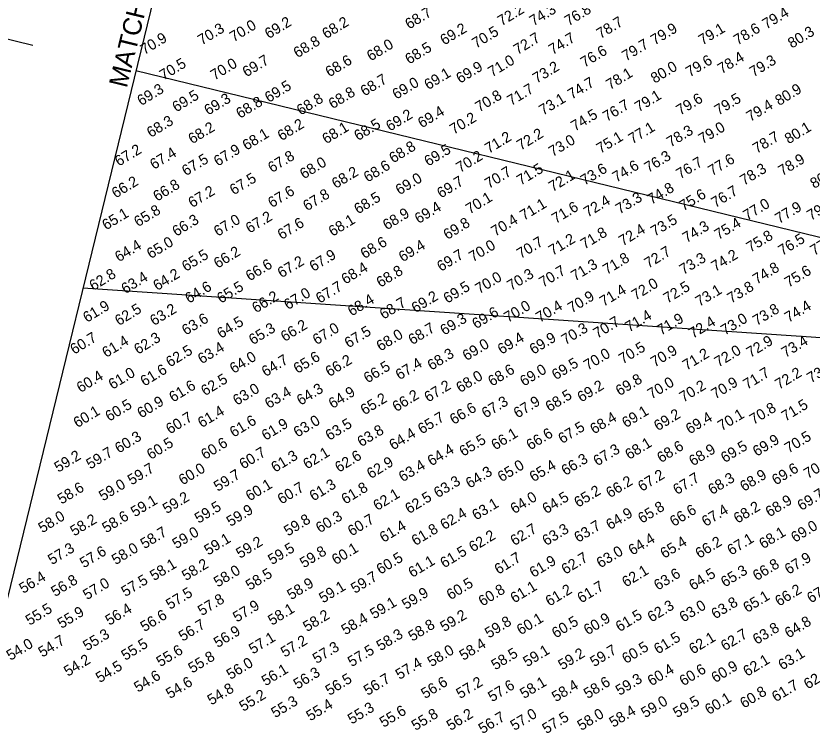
# Model space of a CAD drawing. Extents: x 403671 to 408751, y 1189919 to 1194265.
# Drawn here: x 404728 to 405477, y 1191442 to 1192117 of the extents above; entities that cross this region are included whole.
import ezdxf

# ---------------------------------------------------------------- set-up
doc = ezdxf.new("R2010")
doc.units = 0
for name, color, linetype in [('C-CHAN-POIT', 7, 'Continuous'), ('C-CHAN-WIDE', 7, 'Continuous'), ('V-ALGN-TEXT', 7, 'Continuous'), ('V-ANNO-MATC', 7, 'Continuous'), ('V-ANNO-MATC-IDEN', 7, 'Continuous'), ('V-TOPO-SOUN', 7, 'Continuous')]:
    doc.layers.add(name, color=color, linetype=linetype)

msp = doc.modelspace()

# ---------------------------------------------------------------- linework, layer by layer
at = {"layer": 'C-CHAN-POIT'}
msp.add_line((404840.85, 1192065.98), (406017.44, 1191779.04), dxfattribs=at)
at = {"layer": 'C-CHAN-WIDE'}
msp.add_line((404790.92, 1191861.25), (406017.44, 1191779.04), dxfattribs=at)
at = {"layer": 'V-ALGN-TEXT'}
msp.add_line((404646.55, 1192113.36), (404743.7, 1192089.67), dxfattribs=at)
at = {"layer": 'V-ANNO-MATC'}
msp.add_line((405089.63, 1193086.08), (404704.35, 1191506.27), dxfattribs=at)

# ---------------------------------------------------------------- texts
at = {"layer": 'V-ANNO-MATC-IDEN'}
msp.add_text('MATCHLINE SHEET NO. 024 STA. 6+00 EGMONT CUT-2', height=17.52, rotation=76.29456, dxfattribs=at).set_placement((404832.14, 1192048.75))
at = {"layer": 'V-TOPO-SOUN'}
for s, p in [('72.2 ', (405184.75, 1192107.31)), ('74.3 ', (405214.77, 1192107.31)), ('76.8 ', (405247.78, 1192107.31)), ('68.7 ', (405097.78, 1192104.32)), ('79.4 ', (405433.77, 1192104.32)), ('70.0 ', (404932.78, 1192092.32)), ('69.2 ', (404965.76, 1192095.3)), ('68.2 ', (405019.76, 1192095.3)), ('78.7 ', (405277.76, 1192095.3)), ('70.3 ', (404902.76, 1192089.3)), ('69.2 ', (405130.78, 1192089.3)), ('70.5 ', (405160.77, 1192086.31)), ('79.9 ', (405328.78, 1192089.3)), ('79.1 ', (405373.76, 1192089.3)), ('78.6 ', (405406.77, 1192089.3)), ('80.3 ', (405457.78, 1192086.31)), ('70.9 ', (404848.76, 1192080.31)), ('68.8 ', (404992.76, 1192077.32)), ('72.7 ', (405199.78, 1192080.31)), ('74.7 ', (405232.78, 1192080.31)), ('68.0 ', (405061.75, 1192074.3)), ('68.5 ', (405097.78, 1192071.32)), ('76.6 ', (405262.77, 1192068.3)), ('79.7 ', (405301.78, 1192074.3)), ('78.4 ', (405391.77, 1192062.3)), ('70.5 ', (404866.77, 1192056.29)), ('70.0 ', (404914.77, 1192056.29)), ('69.7 ', (404944.76, 1192059.31)), ('68.6 ', (405022.78, 1192059.31)), ('69.9 ', (405145.77, 1192053.31)), ('71.0 ', (405175.76, 1192059.31)), ('73.2 ', (405217.76, 1192053.31)), ('80.0 ', (405328.78, 1192053.31)), ('79.6 ', (405361.75, 1192059.31)), ('79.3 ', (405421.76, 1192059.31)), ('69.1 ', (405115.76, 1192047.3)), ('78.1 ', (405286.75, 1192047.3)), ('68.7 ', (405055.78, 1192041.3)), ('69.0 ', (405085.77, 1192038.31)), ('74.7 ', (405250.76, 1192038.31)), ('69.3 ', (404845.78, 1192032.31)), ('69.5 ', (404965.76, 1192035.3)), ('71.7 ', (405193.77, 1192032.31)), ('80.9 ', (405445.77, 1192032.31)), ('69.5 ', (404878.78, 1192026.31)), ('69.3 ', (404908.77, 1192023.32)), ('68.8 ', (404995.78, 1192023.32)), ('68.8 ', (405025.76, 1192029.32)), ('70.8 ', (405163.75, 1192026.31)), ('79.1 ', (405313.75, 1192026.31)), ('79.6 ', (405352.76, 1192023.32)), ('79.5 ', (405388.75, 1192023.32)), ('68.8 ', (404938.75, 1192020.3)), ('73.1 ', (405223.76, 1192023.32)), ('76.7 ', (405283.77, 1192017.32)), ('79.4 ', (405418.77, 1192017.32)), ('69.2 ', (405079.76, 1192008.29)), ('69.4 ', (405109.75, 1192011.31)), ('74.5 ', (405253.78, 1192008.29)), ('68.3 ', (404854.77, 1192002.32)), ('70.2 ', (405139.77, 1192005.31)), ('68.2 ', (404893.77, 1191996.32)), ('68.2 ', (404977.76, 1191999.3)), ('68.1 ', (405019.76, 1191996.32)), ('68.5 ', (405049.78, 1191999.3)), ('77.1 ', (405307.78, 1191996.32)), ('79.0 ', (405373.76, 1191996.32)), ('80.1 ', (405454.76, 1191996.32)), ('68.1 ', (404944.76, 1191990.32)), ('71.2 ', (405172.78, 1191987.3)), ('72.2 ', (405202.76, 1191990.32)), ('75.1 ', (405277.76, 1191987.3)), ('78.3 ', (405343.77, 1191993.3)), ('78.7 ', (405424.78, 1191987.3)), ('73.0 ', (405232.78, 1191984.31)), ('67.2 ', (404824.78, 1191975.32)), ('67.4 ', (404857.75, 1191972.3)), ('67.9 ', (404917.76, 1191975.32)), ('68.8 ', (405082.78, 1191978.31)), ('69.5 ', (405115.76, 1191975.32)), ('67.5 ', (404887.77, 1191966.3)), ('67.8 ', (404968.77, 1191969.32)), ('68.0 ', (404998.76, 1191963.31)), ('70.2 ', (405145.77, 1191969.32)), ('76.3 ', (405322.78, 1191969.32)), ('76.7 ', (405352.76, 1191963.31)), ('77.6 ', (405382.78, 1191966.3)), ('78.9 ', (405448.76, 1191966.3)), ('68.6 ', (405058.77, 1191960.3)), ('71.5 ', (405202.76, 1191957.31)), ('73.6 ', (405262.77, 1191957.31)), ('74.6 ', (405292.76, 1191960.3)), ('78.3 ', (405412.77, 1191957.31)), ('67.5 ', (404932.78, 1191948.32)), ('68.2 ', (405028.78, 1191954.32)), ('69.0 ', (405088.75, 1191948.32)), ('70.7 ', (405172.78, 1191954.32)), ('72.1 ', (405232.78, 1191951.31)), ('80.1 ', (405478.78, 1191954.32)), ('66.2 ', (404821.76, 1191945.3)), ('66.8 ', (404860.77, 1191942.32)), ('69.7 ', (405127.76, 1191945.3)), ('67.2 ', (404893.77, 1191936.31)), ('67.6 ', (404968.77, 1191936.31)), ('74.8 ', (405325.76, 1191939.3)), ('75.6 ', (405355.78, 1191933.29)), ('76.7 ', (405385.77, 1191936.31)), ('67.8 ', (405001.78, 1191933.29)), ('68.5 ', (405049.78, 1191930.31)), ('70.1 ', (405154.76, 1191930.31)), ('72.4 ', (405265.76, 1191927.32)), ('73.3 ', (405295.77, 1191930.31)), ('69.4 ', (405106.77, 1191921.32)), ('71.1 ', (405205.78, 1191924.3)), ('71.6 ', (405235.77, 1191921.32)), ('77.0 ', (405415.75, 1191924.3)), ('77.9 ', (405445.77, 1191921.32)), ('79.0 ', (405475.76, 1191924.3)), ('65.1 ', (404812.77, 1191915.32)), ('65.8 ', (404842.76, 1191918.3)), ('67.2 ', (404947.78, 1191912.3)), ('68.9 ', (405076.78, 1191915.32)), ('66.3 ', (404878.78, 1191909.31)), ('67.0 ', (404917.76, 1191909.31)), ('67.6 ', (404977.76, 1191906.29)), ('68.1 ', (405025.76, 1191909.31)), ('69.8 ', (405133.77, 1191906.29)), ('70.4 ', (405178.78, 1191909.31)), ('73.5 ', (405328.78, 1191909.31)), ('75.4 ', (405388.75, 1191906.29)), ('71.8 ', (405262.77, 1191897.3)), ('72.4 ', (405298.76, 1191900.32)), ('74.3 ', (405358.77, 1191903.31)), ('68.6 ', (405055.78, 1191888.31)), ('70.7 ', (405202.76, 1191888.31)), ('71.2 ', (405232.78, 1191891.3)), ('75.8 ', (405418.77, 1191894.32)), ('76.5 ', (405448.76, 1191891.3)), ('77.5 ', (405478.78, 1191891.3)), ('64.4 ', (404824.78, 1191885.3)), ('65.0 ', (404854.77, 1191888.31)), ('69.4 ', (405091.77, 1191885.3)), ('70.0 ', (405157.78, 1191885.3)), ('65.5 ', (404887.77, 1191876.31)), ('66.2 ', (404917.76, 1191879.29)), ('67.9 ', (405007.78, 1191876.31)), ('69.7 ', (405127.76, 1191876.31)), ('72.7 ', (405322.78, 1191879.29)), ('74.2 ', (405385.77, 1191876.31)), ('66.6 ', (404947.78, 1191867.32)), ('67.2 ', (404977.76, 1191870.3)), ('71.3 ', (405253.78, 1191867.32)), ('71.8 ', (405283.77, 1191873.32)), ('73.3 ', (405355.78, 1191873.32)), ('68.4 ', (405037.77, 1191864.3)), ('68.8 ', (405070.78, 1191861.31)), ('70.7 ', (405223.76, 1191861.31)), ('74.8 ', (405424.78, 1191864.3)), ('75.6 ', (405454.76, 1191861.31)), ('62.8 ', (404800.76, 1191858.29)), ('63.4 ', (404830.78, 1191855.31)), ('64.2 ', (404860.77, 1191858.29)), ('70.0 ', (405163.75, 1191855.31)), ('70.3 ', (405193.77, 1191858.29)), ('64.6 ', (404890.76, 1191846.32)), ('65.5 ', (404920.78, 1191846.32)), ('67.7 ', (405013.75, 1191846.32)), ('69.5 ', (405133.77, 1191846.32)), ('72.0 ', (405310.77, 1191849.31)), ('72.5 ', (405340.75, 1191846.32)), ('73.8 ', (405400.76, 1191846.32)), ('66.2 ', (404953.78, 1191837.3)), ('67.0 ', (404983.77, 1191840.32)), ('69.2 ', (405103.78, 1191837.3)), ('70.9 ', (405250.76, 1191837.3)), ('71.4 ', (405280.78, 1191843.3)), ('73.1 ', (405370.77, 1191843.3)), ('68.4 ', (405043.77, 1191834.31)), ('68.7 ', (405073.76, 1191831.29)), ('61.9 ', (404794.76, 1191828.31)), ('62.5 ', (404824.78, 1191825.32)), ('63.2 ', (404857.75, 1191825.32)), ('69.6 ', (405160.77, 1191822.3)), ('70.0 ', (405190.76, 1191828.31)), ('70.4 ', (405220.77, 1191828.31)), ('73.8 ', (405424.78, 1191825.32)), ('74.4 ', (405454.76, 1191828.31)), ('63.6 ', (404887.77, 1191816.3)), ('64.5 ', (404920.78, 1191813.31)), ('69.3 ', (405130.78, 1191816.3)), ('70.7 ', (405274.78, 1191813.31)), ('71.4 ', (405304.76, 1191819.32)), ('71.9 ', (405334.75, 1191816.3)), ('73.0 ', (405394.76, 1191816.3)), ('65.3 ', (404950.76, 1191807.31)), ('66.2 ', (404980.78, 1191810.3)), ('67.0 ', (405010.77, 1191807.31)), ('68.7 ', (405100.76, 1191807.31)), ('70.3 ', (405244.76, 1191807.31)), ('72.4 ', (405364.77, 1191813.31)), ('60.7 ', (404782.75, 1191798.32)), ('67.5 ', (405040.76, 1191804.29)), ('68.0 ', (405070.78, 1191801.31)), ('61.4 ', (404812.77, 1191795.3)), ('62.3 ', (404842.76, 1191798.32)), ('69.0 ', (405151.78, 1191792.32)), ('69.4 ', (405184.75, 1191798.32)), ('69.9 ', (405214.77, 1191798.32)), ('72.9 ', (405418.77, 1191795.3)), ('73.4 ', (405451.78, 1191795.3)), ('62.5 ', (404872.78, 1191786.31)), ('63.4 ', (404902.76, 1191789.3)), ('70.5 ', (405298.76, 1191789.3)), ('70.9 ', (405328.78, 1191786.31)), ('72.0 ', (405388.75, 1191786.31)), ('64.0 ', (404932.78, 1191780.31)), ('64.7 ', (404962.77, 1191777.32)), ('65.6 ', (404992.76, 1191780.31)), ('66.2 ', (405022.78, 1191777.32)), ('68.3 ', (405118.77, 1191783.29)), ('70.0 ', (405265.76, 1191783.29)), ('71.2 ', (405358.77, 1191783.29)), ('61.6 ', (404848.76, 1191768.3)), ('66.5 ', (405058.77, 1191771.32)), ('67.4 ', (405088.75, 1191774.31)), ('68.6 ', (405175.76, 1191768.3)), ('69.5 ', (405235.77, 1191774.31)), ('73.2 ', (405475.76, 1191771.32)), ('60.4 ', (404788.75, 1191762.3)), ('61.0 ', (404818.77, 1191765.32)), ('68.0 ', (405145.77, 1191762.3)), ('69.0 ', (405205.78, 1191768.3)), ('71.7 ', (405415.75, 1191765.32)), ('72.2 ', (405445.77, 1191765.32)), ('61.6 ', (404875.76, 1191753.31)), ('62.5 ', (404905.78, 1191759.31)), ('69.8 ', (405295.77, 1191759.31)), ('70.0 ', (405325.76, 1191756.29)), ('70.9 ', (405385.77, 1191756.29)), ('63.0 ', (404935.77, 1191750.32)), ('63.4 ', (404965.76, 1191747.3)), ('64.3 ', (404995.78, 1191750.32)), ('64.9 ', (405025.76, 1191747.3)), ('67.2 ', (405115.76, 1191753.31)), ('69.2 ', (405259.75, 1191753.31)), ('70.2 ', (405355.78, 1191753.31)), ('65.2 ', (405055.78, 1191741.3)), ('66.2 ', (405085.77, 1191744.32)), ('68.5 ', (405229.76, 1191744.32)), ('60.5 ', (404815.76, 1191735.3)), ('60.9 ', (404845.78, 1191738.31)), ('66.6 ', (405139.77, 1191732.31)), ('67.3 ', (405169.76, 1191738.31)), ('67.9 ', (405199.78, 1191738.31)), ('70.8 ', (405421.76, 1191732.31)), ('71.5 ', (405451.78, 1191735.3)), ('60.1 ', (404785.77, 1191729.29)), ('60.7 ', (404872.78, 1191723.32)), ('61.4 ', (404902.76, 1191729.29)), ('65.7 ', (405109.75, 1191723.32)), ('69.1 ', (405301.78, 1191729.29)), ('69.2 ', (405331.77, 1191726.31)), ('70.1 ', (405391.77, 1191726.31)), ('61.6 ', (404932.78, 1191720.3)), ('61.9 ', (404962.77, 1191717.32)), ('63.0 ', (404992.76, 1191720.3)), ('63.5 ', (405022.78, 1191717.32)), ('68.4 ', (405271.76, 1191723.32)), ('69.4 ', (405361.75, 1191723.32)), ('63.8 ', (405052.76, 1191711.31)), ('66.6 ', (405211.75, 1191708.29)), ('67.5 ', (405241.77, 1191714.3)), ('60.3 ', (404824.78, 1191705.31)), ('64.4 ', (405082.78, 1191708.29)), ('65.5 ', (405148.76, 1191702.32)), ('66.1 ', (405178.78, 1191708.29)), ('69.9 ', (405424.78, 1191702.32)), ('70.5 ', (405454.76, 1191705.31)), ('60.5 ', (404854.77, 1191699.31)), ('60.6 ', (404905.78, 1191699.31)), ('68.1 ', (405304.76, 1191699.31)), ('68.6 ', (405334.75, 1191696.32)), ('69.5 ', (405394.76, 1191696.32)), ('59.2 ', (404767.76, 1191687.3)), ('59.7 ', (404797.78, 1191690.32)), ('60.7 ', (404941.77, 1191690.32)), ('61.3 ', (404971.76, 1191687.3)), ('62.1 ', (405001.78, 1191690.32)), ('62.6 ', (405031.77, 1191687.3)), ('64.4 ', (405118.77, 1191693.3)), ('67.3 ', (405274.78, 1191693.3)), ('68.9 ', (405364.77, 1191693.3)), ('62.9 ', (405061.75, 1191681.29)), ('66.3 ', (405244.76, 1191684.31)), ('70.3 ', (405472.78, 1191681.29)), ('59.7 ', (404836.75, 1191675.32)), ('60.0 ', (404884.75, 1191675.32)), ('63.4 ', (405091.77, 1191678.31)), ('64.3 ', (405154.76, 1191672.3)), ('65.0 ', (405184.75, 1191678.31)), ('65.4 ', (405214.77, 1191678.31)), ('69.6 ', (405442.76, 1191675.32)), ('59.7 ', (404917.76, 1191669.32)), ('67.2 ', (405316.77, 1191669.32)), ('67.7 ', (405349.78, 1191666.3)), ('68.3 ', (405382.78, 1191666.3)), ('68.9 ', (405412.77, 1191669.32)), ('58.6 ', (404770.78, 1191657.31)), ('59.0 ', (404809.75, 1191660.3)), ('60.1 ', (404947.78, 1191660.3)), ('60.7 ', (404977.76, 1191657.31)), ('61.3 ', (405007.78, 1191660.3)), ('61.8 ', (405037.77, 1191657.31)), ('63.3 ', (405124.78, 1191663.31)), ('66.2 ', (405286.75, 1191663.31)), ('62.1 ', (405067.76, 1191651.31)), ('62.5 ', (405097.78, 1191648.32)), ('64.5 ', (405226.78, 1191648.32)), ('65.2 ', (405256.77, 1191654.29)), ('69.7 ', (405466.77, 1191651.31)), ('59.1 ', (404839.77, 1191645.3)), ('59.2 ', (404869.76, 1191648.32)), ('63.1 ', (405160.77, 1191642.32)), ('64.0 ', (405196.76, 1191648.32)), ('68.9 ', (405436.75, 1191645.3)), ('59.5 ', (404899.78, 1191639.3)), ('59.9 ', (404929.76, 1191636.31)), ('65.8 ', (405316.77, 1191639.3)), ('66.6 ', (405346.76, 1191636.31)), ('67.4 ', (405376.78, 1191636.31)), ('68.2 ', (405406.77, 1191639.3)), ('58.0 ', (404752.76, 1191630.31)), ('58.2 ', (404782.75, 1191627.32)), ('58.6 ', (404812.77, 1191630.31)), ('59.8 ', (404983.77, 1191627.32)), ('60.3 ', (405013.75, 1191630.31)), ('60.7 ', (405043.77, 1191627.32)), ('62.4 ', (405130.78, 1191633.3)), ('64.9 ', (405286.75, 1191633.3)), ('61.4 ', (405073.76, 1191621.32)), ('62.7 ', (405196.76, 1191618.3)), ('63.7 ', (405256.77, 1191621.32)), ('69.0 ', (405460.77, 1191621.32)), ('58.7 ', (404848.76, 1191615.32)), ('59.0 ', (404878.78, 1191615.32)), ('61.8 ', (405103.78, 1191618.3)), ('62.2 ', (405157.78, 1191612.3)), ('63.3 ', (405226.78, 1191618.3)), ('68.1 ', (405430.78, 1191615.32)), ('59.1 ', (404908.77, 1191609.31)), ('59.2 ', (404938.75, 1191606.29)), ('64.4 ', (405307.78, 1191609.31)), ('65.4 ', (405337.77, 1191606.29)), ('66.2 ', (405370.77, 1191606.29)), ('67.1 ', (405400.76, 1191609.31)), ('57.3 ', (404761.75, 1191600.32)), ('57.6 ', (404791.77, 1191597.3)), ('58.0 ', (404821.76, 1191600.32)), ('59.5 ', (404968.77, 1191600.32)), ('59.8 ', (404998.76, 1191597.3)), ('60.1 ', (405028.78, 1191600.32)), ('61.5 ', (405130.78, 1191597.3)), ('63.0 ', (405277.76, 1191597.3)), ('60.5 ', (405070.78, 1191591.3)), ('61.7 ', (405181.77, 1191591.3)), ('62.7 ', (405244.76, 1191591.3)), ('67.9 ', (405454.76, 1191591.3)), ('58.1 ', (404857.75, 1191585.3)), ('58.2 ', (404887.77, 1191585.3)), ('61.1 ', (405100.76, 1191588.31)), ('61.9 ', (405214.77, 1191588.31)), ('66.8 ', (405424.78, 1191585.3)), ('58.0 ', (404917.76, 1191579.29)), ('58.5 ', (404947.78, 1191576.31)), ('59.7 ', (405046.76, 1191573.32)), ('62.1 ', (405301.78, 1191579.29)), ('63.6 ', (405331.77, 1191576.31)), ('64.5 ', (405364.77, 1191576.31)), ('65.3 ', (405394.76, 1191579.29)), ('56.4 ', (404734.75, 1191573.32)), ('56.8 ', (404764.77, 1191570.3)), ('57.0 ', (404794.76, 1191567.32)), ('57.5 ', (404830.78, 1191570.3)), ('58.9 ', (404986.75, 1191567.32)), ('60.5 ', (405136.75, 1191567.32)), ('59.1 ', (405016.77, 1191564.3)), ('60.8 ', (405166.77, 1191561.31)), ('61.1 ', (405196.76, 1191564.3)), ('61.2 ', (405229.76, 1191561.31)), ('61.7 ', (405259.75, 1191564.3)), ('66.2 ', (405445.77, 1191561.31)), ('67.2 ', (405475.76, 1191564.3)), ('57.5 ', (404872.78, 1191558.3)), ('57.8 ', (404902.76, 1191552.32)), ('59.9 ', (405094.76, 1191558.3)), ('65.1 ', (405415.75, 1191555.31)), ('57.9 ', (404935.77, 1191546.32)), ('59.1 ', (405064.77, 1191549.31)), ('62.3 ', (405325.76, 1191546.32)), ('63.0 ', (405355.78, 1191546.32)), ('63.8 ', (405385.77, 1191549.31)), ('55.5 ', (404740.76, 1191543.3)), ('55.9 ', (404770.78, 1191540.32)), ('56.4 ', (404815.76, 1191543.3)), ('56.6 ', (404848.76, 1191537.3)), ('58.1 ', (404968.77, 1191543.3)), ('58.2 ', (405001.78, 1191537.3)), ('59.2 ', (405130.78, 1191537.3)), ('61.5 ', (405295.77, 1191537.3)), ('56.7 ', (404884.75, 1191528.31)), ('58.4 ', (405037.77, 1191534.31)), ('59.8 ', (405172.78, 1191531.29)), ('60.1 ', (405202.76, 1191534.31)), ('60.5 ', (405235.77, 1191531.29)), ('60.9 ', (405265.76, 1191534.31)), ('64.8 ', (405454.76, 1191531.29)), ('56.9 ', (404917.76, 1191522.3)), ('58.8 ', (405100.76, 1191528.31)), ('63.8 ', (405424.78, 1191525.32)), ('54.7 ', (404752.76, 1191513.31)), ('55.3 ', (404794.76, 1191519.32)), ('57.1 ', (404950.76, 1191516.3)), ('58.3 ', (405070.78, 1191519.32)), ('61.5 ', (405331.77, 1191516.3)), ('62.1 ', (405364.77, 1191516.3)), ('62.7 ', (405394.76, 1191519.32)), ('54.0 ', (404722.78, 1191510.3)), ('55.5 ', (404830.78, 1191510.3)), ('57.2 ', (404980.78, 1191513.31)), ('57.3 ', (405010.77, 1191507.31)), ('58.4 ', (405148.76, 1191510.3)), ('60.5 ', (405301.78, 1191507.31)), ('55.6 ', (404863.75, 1191504.29)), ('57.5 ', (405043.77, 1191504.29)), ('58.0 ', (405118.77, 1191504.29)), ('58.5 ', (405178.78, 1191501.31)), ('59.1 ', (405208.77, 1191504.29)), ('59.2 ', (405241.77, 1191501.31)), ('59.7 ', (405271.76, 1191504.29)), ('63.1 ', (405448.76, 1191501.31)), ('54.2 ', (404776.78, 1191495.3)), ('55.8 ', (404893.77, 1191498.32)), ('56.0 ', (404929.76, 1191492.32)), ('57.4 ', (405088.75, 1191492.32)), ('62.1 ', (405415.75, 1191495.3)), ('54.5 ', (404806.77, 1191489.3)), ('56.1 ', (404962.77, 1191486.31)), ('60.4 ', (405325.76, 1191486.31)), ('60.6 ', (405355.78, 1191486.31)), ('60.9 ', (405385.77, 1191489.3)), ('54.6 ', (404842.76, 1191480.31)), ('56.3 ', (404992.76, 1191483.3)), ('56.5 ', (405022.78, 1191477.32)), ('56.7 ', (405058.77, 1191477.32)), ('59.3 ', (405295.77, 1191477.32)), ('62.3 ', (405472.78, 1191483.3)), ('54.6 ', (404872.78, 1191474.31)), ('56.6 ', (405112.77, 1191474.31)), ('57.2 ', (405145.77, 1191474.31)), ('57.6 ', (405175.76, 1191471.32)), ('58.1 ', (405205.78, 1191474.31)), ('58.4 ', (405235.77, 1191471.32)), ('58.6 ', (405265.76, 1191474.31)), ('61.7 ', (405442.76, 1191471.32)), ('54.8 ', (404911.75, 1191468.3)), ('55.2 ', (404941.77, 1191462.3)), ('60.8 ', (405412.77, 1191465.32)), ('55.3 ', (404971.76, 1191456.29)), ('59.0 ', (405319.76, 1191456.29)), ('59.5 ', (405349.78, 1191456.29)), ('60.1 ', (405379.76, 1191459.31)), ('55.4 ', (405004.76, 1191453.31)), ('55.3 ', (405043.77, 1191450.32)), ('55.6 ', (405073.76, 1191447.3)), ('58.4 ', (405289.77, 1191447.3)), ('55.8 ', (405103.78, 1191444.32)), ('56.2 ', (405136.75, 1191444.32)), ('56.7 ', (405166.77, 1191441.3)), ('57.0 ', (405196.76, 1191444.32)), ('57.5 ', (405226.78, 1191441.3)), ('58.0 ', (405259.75, 1191444.32))]:
    msp.add_text(s, height=9.996, rotation=31.2939, dxfattribs=at).set_placement(p)

doc.saveas('drawing.dxf')
